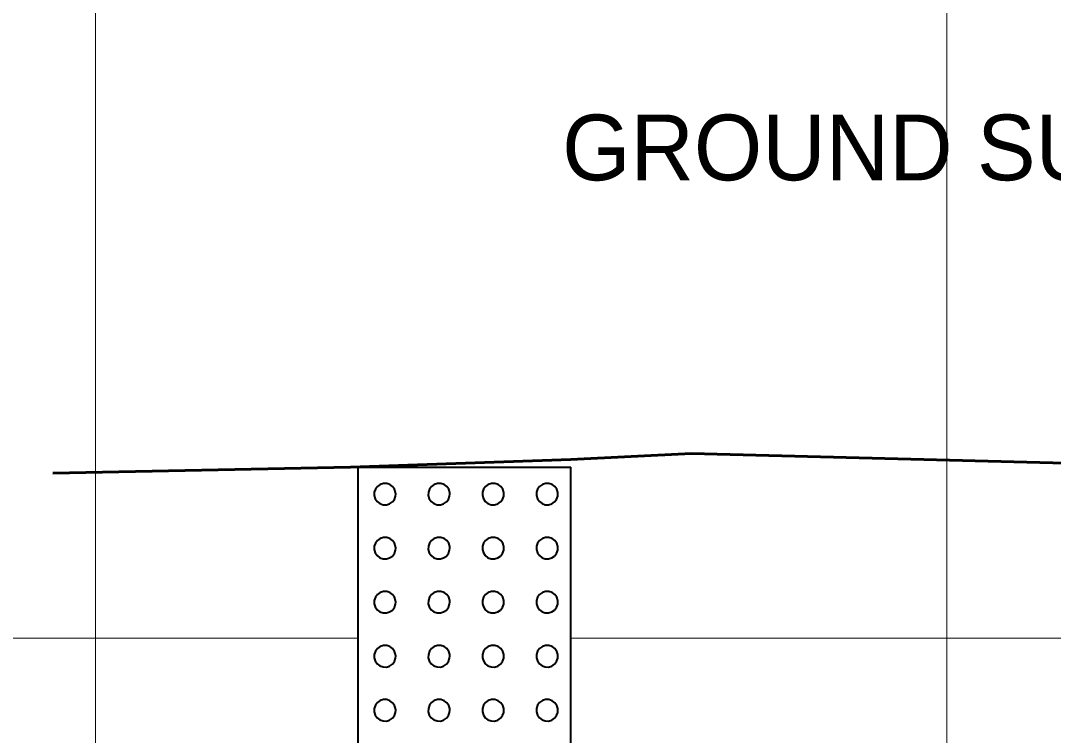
# Model space of a CAD drawing. Extents: x -76 to 974, y -1080 to -735.
# Drawn here: x 132.51 to 144.64, y -933.23 to -924.83 of the extents above; entities that cross this region are included whole.
import ezdxf
from ezdxf.enums import TextEntityAlignment as Align

# ---------------------------------------------------------------- set-up
doc = ezdxf.new("R2010")
doc.units = 0
doc.header["$LTSCALE"] = 0.36
doc.linetypes.add('LONG_DASHED', pattern=[7.5, 6, -1.5])
for name, color, linetype, lineweight in [('27', 7, 'Continuous', 40), ('28', 7, 'LONG_DASHED', 60), ('7', 7, 'Continuous', 13)]:
    doc.layers.add(name, color=color, linetype=linetype, lineweight=lineweight)

msp = doc.modelspace()

# ---------------------------------------------------------------- linework, layer by layer
at = {"layer": '27'}
for p, q in [((136.4742, -930.0789), (136.4742, -941.5789)), ((136.4742, -930.0789), (138.9742, -930.0789)), ((138.9742, -941.5789), (138.9742, -930.0789))]:
    msp.add_line(p, q, dxfattribs=at)
for points in [[(136.9188, -930.3964), (136.9173, -930.3767), (136.9051, -930.339), (136.882, -930.3069), (136.8501, -930.2835), (136.8126, -930.271), (136.773, -930.2707), (136.7353, -930.2825), (136.703, -930.3054), (136.6793, -930.3371), (136.6665, -930.3745), (136.6658, -930.414), (136.6773, -930.4519), (136.6999, -930.4844), (136.7313, -930.5083), (136.7686, -930.5215), (136.8082, -930.5225), (136.8461, -930.5113), (136.8788, -930.489), (136.9031, -930.4578), (136.9165, -930.4206)], [(137.5538, -930.3964), (137.5523, -930.3767), (137.5401, -930.339), (137.517, -930.3069), (137.4851, -930.2835), (137.4476, -930.271), (137.408, -930.2707), (137.3703, -930.2825), (137.338, -930.3054), (137.3143, -930.3371), (137.3015, -930.3745), (137.3008, -930.414), (137.3123, -930.4519), (137.3349, -930.4844), (137.3663, -930.5083), (137.4036, -930.5215), (137.4432, -930.5225), (137.4811, -930.5113), (137.5138, -930.489), (137.5381, -930.4578), (137.5515, -930.4206)], [(138.1888, -930.3964), (138.1873, -930.3767), (138.1751, -930.339), (138.152, -930.3069), (138.1201, -930.2835), (138.0826, -930.271), (138.043, -930.2707), (138.0053, -930.2825), (137.973, -930.3054), (137.9493, -930.3371), (137.9365, -930.3745), (137.9358, -930.414), (137.9473, -930.4519), (137.9699, -930.4844), (138.0013, -930.5083), (138.0386, -930.5215), (138.0782, -930.5225), (138.1161, -930.5113), (138.1488, -930.489), (138.1731, -930.4578), (138.1865, -930.4206)], [(138.8238, -930.3964), (138.8223, -930.3767), (138.8101, -930.339), (138.787, -930.3069), (138.7551, -930.2835), (138.7176, -930.271), (138.678, -930.2707), (138.6403, -930.2825), (138.608, -930.3054), (138.5843, -930.3371), (138.5715, -930.3745), (138.5708, -930.414), (138.5823, -930.4519), (138.6049, -930.4844), (138.6363, -930.5083), (138.6736, -930.5215), (138.7132, -930.5225), (138.7511, -930.5113), (138.7838, -930.489), (138.8081, -930.4578), (138.8215, -930.4206)], [(136.9188, -931.0314), (136.9173, -931.0117), (136.9051, -930.974), (136.882, -930.9419), (136.8501, -930.9185), (136.8126, -930.906), (136.773, -930.9057), (136.7353, -930.9175), (136.703, -930.9404), (136.6793, -930.9721), (136.6665, -931.0095), (136.6658, -931.049), (136.6773, -931.0869), (136.6999, -931.1194), (136.7313, -931.1433), (136.7686, -931.1565), (136.8082, -931.1575), (136.8461, -931.1463), (136.8788, -931.124), (136.9031, -931.0928), (136.9165, -931.0556)], [(137.5538, -931.0314), (137.5523, -931.0117), (137.5401, -930.974), (137.517, -930.9419), (137.4851, -930.9185), (137.4476, -930.906), (137.408, -930.9057), (137.3703, -930.9175), (137.338, -930.9404), (137.3143, -930.9721), (137.3015, -931.0095), (137.3008, -931.049), (137.3123, -931.0869), (137.3349, -931.1194), (137.3663, -931.1433), (137.4036, -931.1565), (137.4432, -931.1575), (137.4811, -931.1463), (137.5138, -931.124), (137.5381, -931.0928), (137.5515, -931.0556)], [(138.1888, -931.0314), (138.1873, -931.0117), (138.1751, -930.974), (138.152, -930.9419), (138.1201, -930.9185), (138.0826, -930.906), (138.043, -930.9057), (138.0053, -930.9175), (137.973, -930.9404), (137.9493, -930.9721), (137.9365, -931.0095), (137.9358, -931.049), (137.9473, -931.0869), (137.9699, -931.1194), (138.0013, -931.1433), (138.0386, -931.1565), (138.0782, -931.1575), (138.1161, -931.1463), (138.1488, -931.124), (138.1731, -931.0928), (138.1865, -931.0556)], [(138.8238, -931.0314), (138.8223, -931.0117), (138.8101, -930.974), (138.787, -930.9419), (138.7551, -930.9185), (138.7176, -930.906), (138.678, -930.9057), (138.6403, -930.9175), (138.608, -930.9404), (138.5843, -930.9721), (138.5715, -931.0095), (138.5708, -931.049), (138.5823, -931.0869), (138.6049, -931.1194), (138.6363, -931.1433), (138.6736, -931.1565), (138.7132, -931.1575), (138.7511, -931.1463), (138.7838, -931.124), (138.8081, -931.0928), (138.8215, -931.0556)], [(136.9188, -931.6664), (136.9173, -931.6467), (136.9051, -931.609), (136.882, -931.5769), (136.8501, -931.5535), (136.8126, -931.541), (136.773, -931.5407), (136.7353, -931.5525), (136.703, -931.5754), (136.6793, -931.6071), (136.6665, -931.6445), (136.6658, -931.684), (136.6773, -931.7219), (136.6999, -931.7544), (136.7313, -931.7783), (136.7686, -931.7915), (136.8082, -931.7925), (136.8461, -931.7813), (136.8788, -931.759), (136.9031, -931.7278), (136.9165, -931.6906)], [(137.5538, -931.6664), (137.5523, -931.6467), (137.5401, -931.609), (137.517, -931.5769), (137.4851, -931.5535), (137.4476, -931.541), (137.408, -931.5407), (137.3703, -931.5525), (137.338, -931.5754), (137.3143, -931.6071), (137.3015, -931.6445), (137.3008, -931.684), (137.3123, -931.7219), (137.3349, -931.7544), (137.3663, -931.7783), (137.4036, -931.7915), (137.4432, -931.7925), (137.4811, -931.7813), (137.5138, -931.759), (137.5381, -931.7278), (137.5515, -931.6906)], [(138.1888, -931.6664), (138.1873, -931.6467), (138.1751, -931.609), (138.152, -931.5769), (138.1201, -931.5535), (138.0826, -931.541), (138.043, -931.5407), (138.0053, -931.5525), (137.973, -931.5754), (137.9493, -931.6071), (137.9365, -931.6445), (137.9358, -931.684), (137.9473, -931.7219), (137.9699, -931.7544), (138.0013, -931.7783), (138.0386, -931.7915), (138.0782, -931.7925), (138.1161, -931.7813), (138.1488, -931.759), (138.1731, -931.7278), (138.1865, -931.6906)], [(138.8238, -931.6664), (138.8223, -931.6467), (138.8101, -931.609), (138.787, -931.5769), (138.7551, -931.5535), (138.7176, -931.541), (138.678, -931.5407), (138.6403, -931.5525), (138.608, -931.5754), (138.5843, -931.6071), (138.5715, -931.6445), (138.5708, -931.684), (138.5823, -931.7219), (138.6049, -931.7544), (138.6363, -931.7783), (138.6736, -931.7915), (138.7132, -931.7925), (138.7511, -931.7813), (138.7838, -931.759), (138.8081, -931.7278), (138.8215, -931.6906)], [(136.9188, -932.3014), (136.9173, -932.2817), (136.9051, -932.244), (136.882, -932.2119), (136.8501, -932.1885), (136.8126, -932.176), (136.773, -932.1757), (136.7353, -932.1875), (136.703, -932.2104), (136.6793, -932.2421), (136.6665, -932.2795), (136.6658, -932.319), (136.6773, -932.3569), (136.6999, -932.3894), (136.7313, -932.4133), (136.7686, -932.4265), (136.8082, -932.4275), (136.8461, -932.4163), (136.8788, -932.394), (136.9031, -932.3628), (136.9165, -932.3256)], [(137.5538, -932.3014), (137.5523, -932.2817), (137.5401, -932.244), (137.517, -932.2119), (137.4851, -932.1885), (137.4476, -932.176), (137.408, -932.1757), (137.3703, -932.1875), (137.338, -932.2104), (137.3143, -932.2421), (137.3015, -932.2795), (137.3008, -932.319), (137.3123, -932.3569), (137.3349, -932.3894), (137.3663, -932.4133), (137.4036, -932.4265), (137.4432, -932.4275), (137.4811, -932.4163), (137.5138, -932.394), (137.5381, -932.3628), (137.5515, -932.3256)], [(138.1888, -932.3014), (138.1873, -932.2817), (138.1751, -932.244), (138.152, -932.2119), (138.1201, -932.1885), (138.0826, -932.176), (138.043, -932.1757), (138.0053, -932.1875), (137.973, -932.2104), (137.9493, -932.2421), (137.9365, -932.2795), (137.9358, -932.319), (137.9473, -932.3569), (137.9699, -932.3894), (138.0013, -932.4133), (138.0386, -932.4265), (138.0782, -932.4275), (138.1161, -932.4163), (138.1488, -932.394), (138.1731, -932.3628), (138.1865, -932.3256)], [(138.8238, -932.3014), (138.8223, -932.2817), (138.8101, -932.244), (138.787, -932.2119), (138.7551, -932.1885), (138.7176, -932.176), (138.678, -932.1757), (138.6403, -932.1875), (138.608, -932.2104), (138.5843, -932.2421), (138.5715, -932.2795), (138.5708, -932.319), (138.5823, -932.3569), (138.6049, -932.3894), (138.6363, -932.4133), (138.6736, -932.4265), (138.7132, -932.4275), (138.7511, -932.4163), (138.7838, -932.394), (138.8081, -932.3628), (138.8215, -932.3256)], [(136.9188, -932.9364), (136.9173, -932.9167), (136.9051, -932.879), (136.882, -932.8469), (136.8501, -932.8235), (136.8126, -932.811), (136.773, -932.8107), (136.7353, -932.8225), (136.703, -932.8454), (136.6793, -932.8771), (136.6665, -932.9145), (136.6658, -932.954), (136.6773, -932.9919), (136.6999, -933.0244), (136.7313, -933.0483), (136.7686, -933.0615), (136.8082, -933.0625), (136.8461, -933.0513), (136.8788, -933.029), (136.9031, -932.9978), (136.9165, -932.9606)], [(137.5538, -932.9364), (137.5523, -932.9167), (137.5401, -932.879), (137.517, -932.8469), (137.4851, -932.8235), (137.4476, -932.811), (137.408, -932.8107), (137.3703, -932.8225), (137.338, -932.8454), (137.3143, -932.8771), (137.3015, -932.9145), (137.3008, -932.954), (137.3123, -932.9919), (137.3349, -933.0244), (137.3663, -933.0483), (137.4036, -933.0615), (137.4432, -933.0625), (137.4811, -933.0513), (137.5138, -933.029), (137.5381, -932.9978), (137.5515, -932.9606)], [(138.1888, -932.9364), (138.1873, -932.9167), (138.1751, -932.879), (138.152, -932.8469), (138.1201, -932.8235), (138.0826, -932.811), (138.043, -932.8107), (138.0053, -932.8225), (137.973, -932.8454), (137.9493, -932.8771), (137.9365, -932.9145), (137.9358, -932.954), (137.9473, -932.9919), (137.9699, -933.0244), (138.0013, -933.0483), (138.0386, -933.0615), (138.0782, -933.0625), (138.1161, -933.0513), (138.1488, -933.029), (138.1731, -932.9978), (138.1865, -932.9606)], [(138.8238, -932.9364), (138.8223, -932.9167), (138.8101, -932.879), (138.787, -932.8469), (138.7551, -932.8235), (138.7176, -932.811), (138.678, -932.8107), (138.6403, -932.8225), (138.608, -932.8454), (138.5843, -932.8771), (138.5715, -932.9145), (138.5708, -932.954), (138.5823, -932.9919), (138.6049, -933.0244), (138.6363, -933.0483), (138.6736, -933.0615), (138.7132, -933.0625), (138.7511, -933.0513), (138.7838, -933.029), (138.8081, -932.9978), (138.8215, -932.9606)]]:
    msp.add_lwpolyline(points, close=True, dxfattribs=at)
at = {"layer": '28', "linetype": 'Continuous'}
msp.add_lwpolyline([(132.8909, -930.15), (136.3853, -930.0789), (138.9742, -929.99), (140.3909, -929.92), (145.3909, -930.05), (150.7242, -928.09), (154.3909, -927.86), (154.3909, -928.34), (167.3909, -927.18), (180.7245, -926.63), (183.0579, -926.89), (188.7245, -927.1), (193.0578, -927.9), (195.3912, -929.1789), (196.6412, -929.09), (200.7245, -929.03)], dxfattribs=at)
at = {"layer": '7'}
for p, q in [((133.3912, -1033.3123), (133.3912, -895.7205)), ((143.3912, -933.9727), (143.3912, -895.7205)), ((116.7824, -932.09), (136.4742, -932.09)), ((138.9742, -932.09), (194.1412, -932.09))]:
    msp.add_line(p, q, dxfattribs=at)

# ---------------------------------------------------------------- texts
at = {"layer": '27'}
msp.add_text('GROUND SURFACE', height=0.7717, dxfattribs=at).set_placement((143.7744, -926.71), align=Align.CENTER)

doc.saveas('drawing.dxf')
